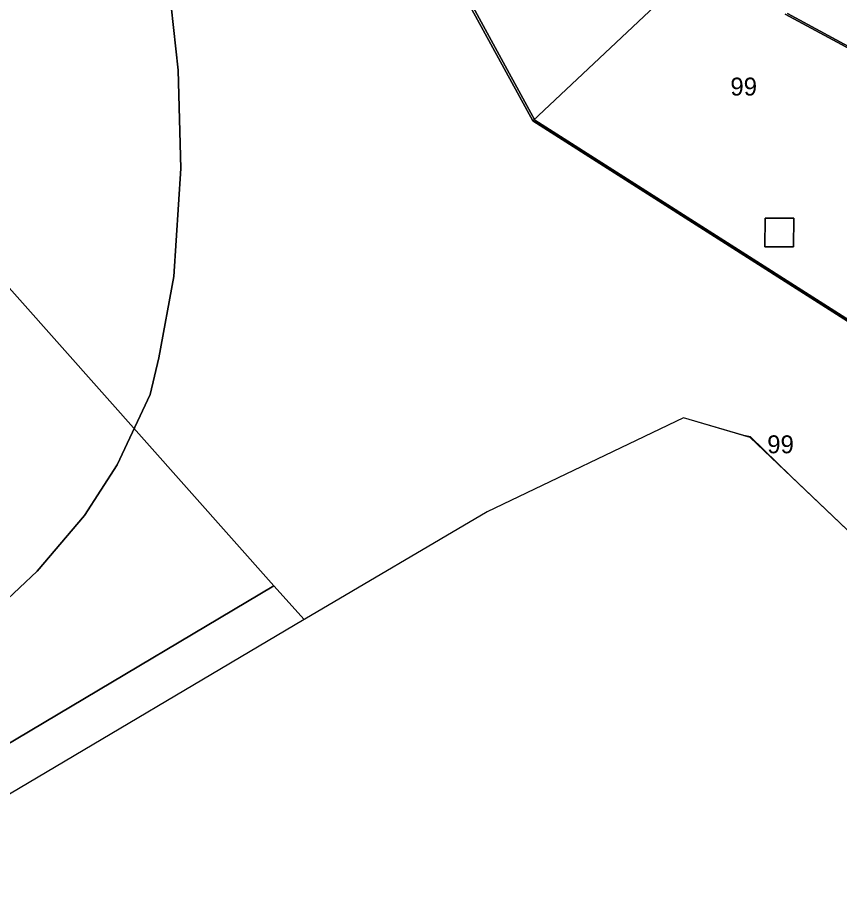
# Model space of a CAD drawing. Extents: x -535894 to -532834, y -1165802 to -1163645.
# Drawn here: x -533641.6 to -533412.1, y -1165150.8 to -1164904.7 of the extents above; entities that cross this region are included whole.
import ezdxf

# ---------------------------------------------------------------- set-up
doc = ezdxf.new("R2010")
doc.units = 0
for name, color, linetype in [('95590013', 7, 'Continuous'), ('95600013', 7, 'Continuous'), ('95620013', 7, 'Continuous'), ('95640013', 7, 'Continuous'), ('95660013', 7, 'Continuous')]:
    doc.layers.add(name, color=color, linetype=linetype)

msp = doc.modelspace()

# ---------------------------------------------------------------- linework, layer by layer
at = {"layer": '95590013'}
for points in [[(-533755.71, -1164908.94), (-533737.9, -1164874.36), (-533570, -1165063.27), (-533698.37, -1165139.6), (-533742.77, -1165073.32), (-533781.22, -1164997.48), (-533775.32, -1164984.22), (-533774.28, -1164976.84), (-533772.59, -1164965.85), (-533761.58, -1164933.18)], [(-533570, -1165063.27), (-533561.52, -1165072.67), (-533646.35, -1165122.98), (-533690.81, -1165150.82), (-533698.37, -1165139.6)]]:
    msp.add_lwpolyline(points, close=True, dxfattribs=at)
at = {"layer": '95600013'}
msp.add_lwpolyline([(-533670.19, -1164839.35), (-533626.96, -1164831.3), (-533613.25, -1164834.55), (-533603.37, -1164835.56), (-533596.46, -1164833.25), (-533553.28, -1164851.89), (-533522.7, -1164887.69), (-533497.72, -1164933.47), (-533391.12, -1165001.26), (-533381.33, -1164991.55), (-533372.98, -1165023.48), (-533364.81, -1165056.97), (-533353.28, -1165054.53), (-533343.29, -1165052.42), (-533340.42, -1165060.46), (-533373.45, -1165068.48), (-533390.5, -1165066.09), (-533436.96, -1165021.83), (-533455.65, -1165016.42), (-533510.43, -1165042.58), (-533561.35, -1165072.56), (-533561.52, -1165072.67), (-533570, -1165063.27), (-533737.9, -1164874.36)], dxfattribs=at)
at = {"layer": '95620013'}
msp.add_lwpolyline([(-533516.99, -1164867.54), (-533454.32, -1164892.58), (-533497.72, -1164933.47), (-533522.7, -1164887.69), (-533553.28, -1164851.89)], close=True, dxfattribs=at)
at = {"layer": '95640013'}
for points in [[(-533427.21, -1164903.65), (-533369.34, -1164934.9), (-533368.62, -1164936.59), (-533365.53, -1164943.74), (-533362.54, -1164951.44), (-533359.28, -1164958.21), (-533355.82, -1164966.23), (-533350.5, -1164960.74), (-533351.5, -1164950.92), (-533354.34, -1164943.84), (-533356.31, -1164938.57), (-533351.86, -1164939.38), (-533351.34, -1164940.58), (-533349.07, -1164947.93), (-533348.45, -1164950.88), (-533350.73, -1164975.81), (-533352.5, -1164976.21), (-533356.25, -1164977.03), (-533369.51, -1164979.95), (-533383.55, -1164983.05), (-533381.33, -1164991.55), (-533391.12, -1165001.26), (-533497.72, -1164933.47), (-533454.32, -1164892.58)], [(-533369.34, -1164934.9), (-533427.21, -1164903.65)]]:
    msp.add_lwpolyline(points, dxfattribs=at)
for points in [[(-533432.79, -1164960.61), (-533432.86, -1164968.61), (-533424.86, -1164968.68), (-533424.79, -1164960.67)], [(-533432.79, -1164960.61), (-533424.79, -1164960.67), (-533424.86, -1164968.68), (-533432.86, -1164968.61)]]:
    msp.add_lwpolyline(points, close=True, dxfattribs=at)
at = {"layer": '95660013'}
for points in [[(-533643.883, -1164847.81), (-533633.62, -1164846.14), (-533623.11, -1164844.309), (-533611.08, -1164860.71), (-533605.11, -1164874.33), (-533599.37, -1164895.361), (-533596.75, -1164919.33), (-533596.03, -1164946.8), (-533597.94, -1164976.91), (-533602.16, -1164999.6), (-533604.55, -1165009.88), (-533613.79, -1165029.47), (-533622.875, -1165043.634), (-533636.09, -1165059.169), (-533650.981, -1165073.11)], [(-533522.095, -1164887.508), (-533497.114, -1164933.287), (-533390.513, -1165001.084), (-533380.721, -1164991.378), (-533382.945, -1164982.87), (-533368.897, -1164979.776), (-533355.644, -1164976.854), (-533351.891, -1164976.035), (-533350.116, -1164975.638), (-533348.56, -1164958.614), (-533347.837, -1164950.711), (-533347.512, -1164947.155), (-533346.817, -1164939.999), (-533349.698, -1164939.487), (-533351.256, -1164939.202), (-533355.068, -1164938.512), (-533355.703, -1164938.397), (-533359.057, -1164937.792), (-533365.083, -1164936.699), (-533368.736, -1164934.723), (-533382.308, -1164927.394), (-533426.603, -1164903.475)], [(-533426.603, -1164903.475), (-533382.308, -1164927.394), (-533368.736, -1164934.723), (-533365.083, -1164936.699), (-533359.057, -1164937.792), (-533355.703, -1164938.397), (-533355.068, -1164938.512), (-533351.256, -1164939.202), (-533349.698, -1164939.487), (-533346.817, -1164939.999), (-533347.512, -1164947.155), (-533347.837, -1164950.711), (-533348.56, -1164958.614), (-533350.116, -1164975.638), (-533351.891, -1164976.035), (-533355.644, -1164976.854), (-533368.897, -1164979.776), (-533382.945, -1164982.87), (-533380.721, -1164991.378), (-533390.513, -1165001.084), (-533497.114, -1164933.287), (-533522.095, -1164887.508)], [(-533650.981, -1165073.11), (-533636.09, -1165059.169), (-533622.875, -1165043.634), (-533613.79, -1165029.47), (-533604.55, -1165009.88), (-533602.16, -1164999.6), (-533597.94, -1164976.91), (-533596.03, -1164946.8), (-533596.75, -1164919.33), (-533599.37, -1164895.361)], [(-533390.5, -1165066.09), (-533425.693, -1165032.564), (-533436.87, -1165021.7), (-533438.763, -1165021.308), (-533455.65, -1165016.42), (-533510.43, -1165042.58), (-533561.35, -1165072.56), (-533561.52, -1165072.67), (-533646.35, -1165122.98)]]:
    msp.add_lwpolyline(points, dxfattribs=at)
msp.add_lwpolyline([(-533436.87, -1165021.7), (-533425.693, -1165032.564), (-533436.96, -1165021.83), (-533438.763, -1165021.308)], close=True, dxfattribs=at)

# ---------------------------------------------------------------- texts
for p in [(-533442.519, -1164926.393), (-533432.228, -1165026.275)]:
    msp.add_text('99', height=5, rotation=0, dxfattribs=at).set_placement(p)

doc.saveas('drawing.dxf')
